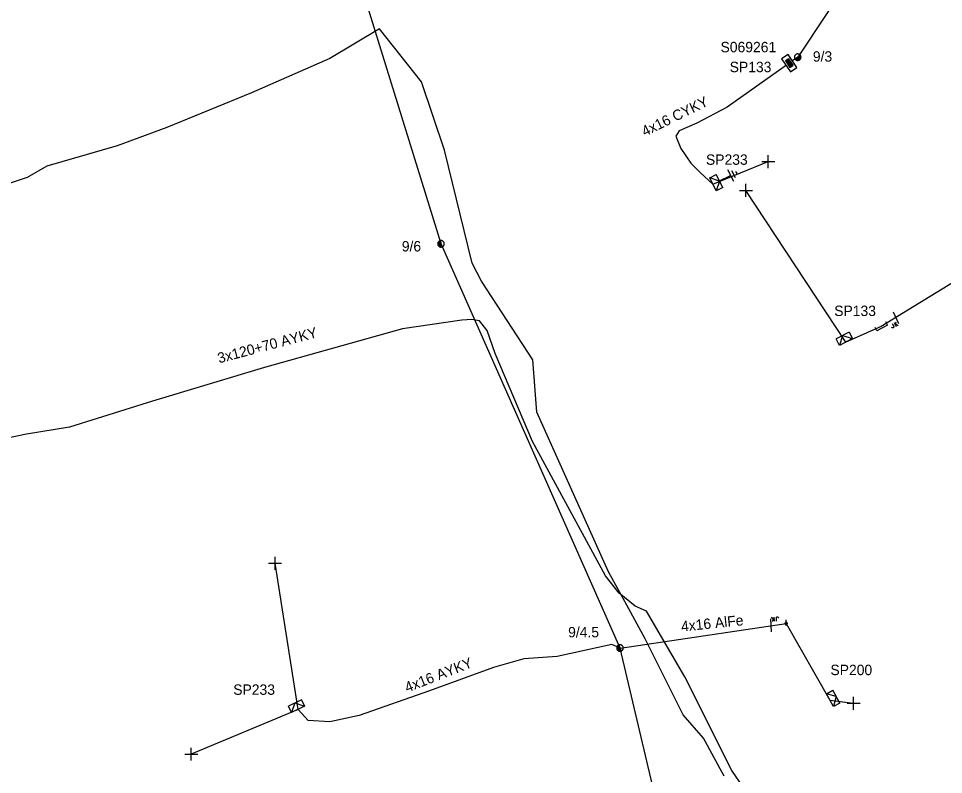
# Model space of a CAD drawing. Extents: x -717562 to -713845, y -1151196 to -1143903.
# Drawn here: x -717170 to -717081, y -1144446.2 to -1144373.5 of the extents above; entities that cross this region are included whole.
import ezdxf

# ---------------------------------------------------------------- set-up
doc = ezdxf.new("R2010")
doc.units = 0
for name, color, linetype in [('Vrstva 1', 7, 'Continuous'), ('Vrstva 12', 7, 'Continuous'), ('Vrstva 13', 7, 'Continuous'), ('Vrstva 14', 7, 'Continuous'), ('Vrstva 15', 7, 'Continuous'), ('Vrstva 18', 7, 'Continuous'), ('Vrstva 2', 7, 'Continuous'), ('Vrstva 28', 7, 'Continuous'), ('Vrstva 29', 7, 'Continuous'), ('Vrstva 30', 7, 'Continuous'), ('Vrstva 31', 7, 'Continuous'), ('Vrstva 33', 7, 'Continuous'), ('Vrstva 34', 7, 'Continuous'), ('Vrstva 4', 7, 'Continuous'), ('Vrstva 52', 7, 'Continuous'), ('Vrstva 53', 7, 'Continuous'), ('Vrstva 54', 7, 'Continuous'), ('Vrstva 59', 7, 'Continuous'), ('Vrstva 8', 7, 'Continuous'), ('Vrstva 9', 7, 'Continuous')]:
    doc.layers.add(name, color=color, linetype=linetype)

# ---------------------------------------------------------------- blocks, each defined once
blk = doc.blocks.new('NN440')
at = {"layer": 'Vrstva 2'}
for points in [[(0.63, 0), (0.63, 0.06), (0.62, 0.13), (0.6, 0.19), (0.58, 0.25), (0.55, 0.31), (0.51, 0.37), (0.47, 0.42), (0.42, 0.46), (0.37, 0.51), (0.32, 0.54), (0.26, 0.57), (0.2, 0.59), (0.13, 0.61), (0.07, 0.62), (0, 0.63), (-0.06, 0.62), (-0.13, 0.61), (-0.19, 0.59), (-0.26, 0.57), (-0.31, 0.54), (-0.37, 0.51), (-0.42, 0.46), (-0.47, 0.42), (-0.51, 0.37), (-0.54, 0.31), (-0.57, 0.25), (-0.6, 0.19), (-0.62, 0.13), (-0.63, 0.06), (-0.63, 0), (-0.63, -0.07), (-0.62, -0.14), (-0.6, -0.2), (-0.57, -0.26), (-0.54, -0.32), (-0.51, -0.37), (-0.47, -0.43), (-0.42, -0.47), (-0.37, -0.51), (-0.31, -0.55), (-0.26, -0.58), (-0.19, -0.6), (-0.13, -0.62), (-0.06, -0.63), (0, -0.63), (0.07, -0.63), (0.13, -0.62), (0.2, -0.6), (0.26, -0.58), (0.32, -0.55), (0.37, -0.51), (0.42, -0.47), (0.47, -0.43), (0.51, -0.37), (0.55, -0.32), (0.58, -0.26), (0.6, -0.2), (0.62, -0.14), (0.63, -0.07), (0.63, 0)], [(-0.63, 0), (0.63, 0)], [(-0.6, -0.18), (0.57, -0.18)], [(-0.51, -0.32), (0.5, -0.32)], [(-0.37, -0.47), (0.35, -0.47)]]:
    blk.add_lwpolyline(points, dxfattribs=at)
blk = doc.blocks.new('NN840')
at = {"layer": 'Vrstva 15'}
for points in [[(0.003, 0.619), (0.003, -0.631)], [(-0.745, -0.71), (-0.745, -0.66)], [(-0.73, -0.764), (-0.745, -0.71)], [(-0.657, -0.798), (-0.73, -0.764)], [(-0.627, -0.798), (-0.657, -0.798)], [(-0.558, -0.764), (-0.627, -0.798)], [(-0.538, -0.71), (-0.558, -0.764)], [(-0.538, -0.385), (-0.538, -0.71)], [(-0.332, -0.385), (-0.332, -0.798)], [(-0.332, -0.641), (-0.125, -0.385)], [(-0.263, -0.557), (-0.091, -0.798)]]:
    blk.add_lwpolyline(points, dxfattribs=at)
blk = doc.blocks.new('NN800')
at = {"layer": 'Vrstva 1'}
for points in [[(-0.442, 0.442), (0.442, -0.442)], [(-0.442, -0.442), (0.442, 0.442)]]:
    blk.add_lwpolyline(points, dxfattribs=at)
blk = doc.blocks.new('NN620')
at = {"layer": 'Vrstva 8'}
for points in [[(0.752, 0.004), (-0.748, 0.004)], [(-0.748, 0.004), (-0.748, -0.746)], [(0.752, -0.746), (0.752, 0.004)], [(-0.748, -0.746), (0.752, -0.746)], [(0.368, -0.18), (-0.376, -0.18)], [(-0.376, -0.18), (-0.376, -0.558)], [(-0.376, -0.558), (0.368, -0.558)], [(0.321, -0.227), (-0.329, -0.227)], [(-0.329, -0.227), (-0.329, -0.51)], [(-0.329, -0.51), (0.321, -0.51)], [(0.274, -0.274), (-0.281, -0.274)], [(-0.281, -0.274), (-0.281, -0.463)], [(-0.281, -0.463), (0.274, -0.463)], [(0.227, -0.321), (-0.234, -0.321)], [(-0.234, -0.321), (-0.234, -0.416)], [(-0.234, -0.416), (0.227, -0.416)], [(-0.193, -0.369), (0.185, -0.369)], [(0.227, -0.416), (0.227, -0.321)], [(0.274, -0.463), (0.274, -0.274)], [(0.321, -0.51), (0.321, -0.227)], [(0.368, -0.558), (0.368, -0.18)]]:
    blk.add_lwpolyline(points, dxfattribs=at)
blk = doc.blocks.new('NN630')
at = {"layer": 'Vrstva 9'}
for points in [[(-0.003, -0.7), (-0.703, 0)], [(-0.703, -0.7), (-0.703, 0), (0.697, 0), (0.697, -0.7)], [(-0.703, -0.7), (0.697, -0.7)], [(-0.003, -0.7), (0.697, 0)]]:
    blk.add_lwpolyline(points, dxfattribs=at)
blk = doc.blocks.new('NN810')
at = {"layer": 'Vrstva 14'}
for points in [[(0.004, -0.64), (0.004, -1.89)], [(0.629, -1.89), (-0.621, -1.89)], [(0.388, -2.2), (-0.399, -2.2)], [(0.004, -2.515), (-0.124, -2.515)], [(0.137, -2.515), (0.004, -2.515)]]:
    blk.add_lwpolyline(points, dxfattribs=at)
blk = doc.blocks.new('NN500')
at = {"layer": 'Vrstva 2'}
for points in [[(0, -0.24), (0.02, -0.23), (0.05, -0.23), (0.07, -0.22), (0.09, -0.22), (0.12, -0.2), (0.14, -0.19), (0.16, -0.18), (0.17, -0.16), (0.19, -0.14), (0.2, -0.12), (0.21, -0.1), (0.22, -0.07), (0.23, -0.05), (0.23, -0.02), (0.23, 0), (0.23, 0.02), (0.23, 0.05), (0.22, 0.07), (0.21, 0.1), (0.2, 0.12), (0.19, 0.14), (0.17, 0.16), (0.16, 0.17), (0.14, 0.19), (0.12, 0.2), (0.09, 0.21), (0.07, 0.22), (0.05, 0.23), (0.02, 0.23), (0, 0.23), (-0.03, 0.23), (-0.05, 0.23), (-0.07, 0.22), (-0.1, 0.21), (-0.12, 0.2), (-0.14, 0.19), (-0.16, 0.17), (-0.18, 0.16), (-0.19, 0.14), (-0.2, 0.12), (-0.22, 0.1), (-0.22, 0.07), (-0.23, 0.05), (-0.23, 0.02), (-0.24, 0), (-0.23, -0.02), (-0.23, -0.05), (-0.22, -0.07), (-0.22, -0.1), (-0.2, -0.12), (-0.19, -0.14), (-0.18, -0.16), (-0.16, -0.18), (-0.14, -0.19), (-0.12, -0.2), (-0.1, -0.22), (-0.07, -0.22), (-0.05, -0.23), (-0.03, -0.23), (0, -0.24)], [(0, -0.24), (0.02, -0.23), (0.05, -0.23), (0.07, -0.22), (0.09, -0.22), (0.12, -0.2), (0.14, -0.19), (0.16, -0.18), (0.17, -0.16), (0.19, -0.14), (0.2, -0.12), (0.21, -0.1), (0.22, -0.07), (0.23, -0.05), (0.23, -0.02), (0.23, 0), (0.23, 0.02), (0.23, 0.05), (0.22, 0.07), (0.21, 0.1), (0.2, 0.12), (0.19, 0.14), (0.17, 0.16), (0.16, 0.17), (0.14, 0.19), (0.12, 0.2), (0.09, 0.21), (0.07, 0.22), (0.05, 0.23), (0.02, 0.23), (0, 0.23), (-0.03, 0.23), (-0.05, 0.23), (-0.07, 0.22), (-0.1, 0.21), (-0.12, 0.2), (-0.14, 0.19), (-0.16, 0.17), (-0.18, 0.16), (-0.19, 0.14), (-0.2, 0.12), (-0.22, 0.1), (-0.22, 0.07), (-0.23, 0.05), (-0.23, 0.02), (-0.24, 0), (-0.23, -0.02), (-0.23, -0.05), (-0.22, -0.07), (-0.22, -0.1), (-0.2, -0.12), (-0.19, -0.14), (-0.18, -0.16), (-0.16, -0.18), (-0.14, -0.19), (-0.12, -0.2), (-0.1, -0.22), (-0.07, -0.22), (-0.05, -0.23), (-0.03, -0.23), (0, -0.24)], [(0, -0.21), (0.02, -0.2), (0.04, -0.2), (0.06, -0.2), (0.08, -0.19), (0.1, -0.18), (0.12, -0.17), (0.14, -0.15), (0.15, -0.14), (0.16, -0.12), (0.18, -0.1), (0.19, -0.08), (0.19, -0.06), (0.2, -0.04), (0.2, -0.02), (0.2, 0), (0.2, 0.02), (0.2, 0.04), (0.19, 0.06), (0.19, 0.08), (0.18, 0.1), (0.16, 0.12), (0.15, 0.14), (0.14, 0.15), (0.12, 0.17), (0.1, 0.18), (0.08, 0.19), (0.06, 0.19), (0.04, 0.2), (0.02, 0.2), (0, 0.2), (-0.02, 0.2), (-0.04, 0.2), (-0.06, 0.19), (-0.08, 0.19), (-0.1, 0.18), (-0.12, 0.17), (-0.14, 0.15), (-0.15, 0.14), (-0.17, 0.12), (-0.18, 0.1), (-0.19, 0.08), (-0.2, 0.06), (-0.2, 0.04), (-0.21, 0.02), (-0.21, 0), (-0.21, -0.02), (-0.2, -0.04), (-0.2, -0.06), (-0.19, -0.08), (-0.18, -0.1), (-0.17, -0.12), (-0.15, -0.14), (-0.14, -0.15), (-0.12, -0.17), (-0.1, -0.18), (-0.08, -0.19), (-0.06, -0.2), (-0.04, -0.2), (-0.02, -0.2), (0, -0.21)], [(0, -0.18), (0.02, -0.18), (0.04, -0.17), (0.05, -0.17), (0.07, -0.16), (0.09, -0.15), (0.1, -0.14), (0.12, -0.13), (0.13, -0.12), (0.14, -0.1), (0.15, -0.09), (0.16, -0.07), (0.17, -0.05), (0.17, -0.04), (0.17, -0.02), (0.17, 0), (0.17, 0.02), (0.17, 0.04), (0.17, 0.05), (0.16, 0.07), (0.15, 0.09), (0.14, 0.1), (0.13, 0.12), (0.12, 0.13), (0.1, 0.14), (0.09, 0.15), (0.07, 0.16), (0.05, 0.17), (0.04, 0.17), (0.02, 0.17), (0, 0.18), (-0.02, 0.17), (-0.04, 0.17), (-0.06, 0.17), (-0.07, 0.16), (-0.09, 0.15), (-0.1, 0.14), (-0.12, 0.13), (-0.13, 0.12), (-0.14, 0.1), (-0.15, 0.09), (-0.16, 0.07), (-0.17, 0.05), (-0.17, 0.04), (-0.18, 0.02), (-0.18, 0), (-0.18, -0.02), (-0.17, -0.04), (-0.17, -0.05), (-0.16, -0.07), (-0.15, -0.09), (-0.14, -0.1), (-0.13, -0.12), (-0.12, -0.13), (-0.1, -0.14), (-0.09, -0.15), (-0.07, -0.16), (-0.06, -0.17), (-0.04, -0.17), (-0.02, -0.18), (0, -0.18)], [(0, -0.15), (0.01, -0.15), (0.03, -0.14), (0.04, -0.14), (0.06, -0.13), (0.07, -0.13), (0.08, -0.12), (0.1, -0.11), (0.11, -0.1), (0.12, -0.09), (0.13, -0.07), (0.13, -0.06), (0.14, -0.05), (0.14, -0.03), (0.14, -0.02), (0.14, 0), (0.14, 0.01), (0.14, 0.03), (0.14, 0.04), (0.13, 0.06), (0.13, 0.07), (0.12, 0.09), (0.11, 0.1), (0.1, 0.11), (0.08, 0.12), (0.07, 0.13), (0.06, 0.13), (0.04, 0.14), (0.03, 0.14), (0.01, 0.14), (0, 0.15), (-0.02, 0.14), (-0.03, 0.14), (-0.05, 0.14), (-0.06, 0.13), (-0.07, 0.13), (-0.09, 0.12), (-0.1, 0.11), (-0.11, 0.1), (-0.12, 0.09), (-0.13, 0.07), (-0.13, 0.06), (-0.14, 0.04), (-0.14, 0.03), (-0.15, 0.01), (-0.15, 0), (-0.15, -0.02), (-0.14, -0.03), (-0.14, -0.05), (-0.13, -0.06), (-0.13, -0.07), (-0.12, -0.09), (-0.11, -0.1), (-0.1, -0.11), (-0.09, -0.12), (-0.07, -0.13), (-0.06, -0.13), (-0.05, -0.14), (-0.03, -0.14), (-0.02, -0.15), (0, -0.15)], [(0, -0.12), (0.01, -0.12), (0.02, -0.11), (0.03, -0.11), (0.05, -0.11), (0.06, -0.1), (0.07, -0.09), (0.08, -0.09), (0.09, -0.08), (0.09, -0.07), (0.1, -0.06), (0.11, -0.05), (0.11, -0.04), (0.11, -0.02), (0.11, -0.01), (0.12, 0), (0.11, 0.01), (0.11, 0.02), (0.11, 0.04), (0.11, 0.05), (0.1, 0.06), (0.09, 0.07), (0.09, 0.08), (0.08, 0.09), (0.07, 0.09), (0.06, 0.1), (0.05, 0.11), (0.03, 0.11), (0.02, 0.11), (0.01, 0.12), (0, 0.12), (-0.01, 0.12), (-0.03, 0.11), (-0.04, 0.11), (-0.05, 0.11), (-0.06, 0.1), (-0.07, 0.09), (-0.08, 0.09), (-0.09, 0.08), (-0.1, 0.07), (-0.1, 0.06), (-0.11, 0.05), (-0.11, 0.04), (-0.12, 0.02), (-0.12, 0.01), (-0.12, 0), (-0.12, -0.01), (-0.12, -0.02), (-0.11, -0.04), (-0.11, -0.05), (-0.1, -0.06), (-0.1, -0.07), (-0.09, -0.08), (-0.08, -0.09), (-0.07, -0.09), (-0.06, -0.1), (-0.05, -0.11), (-0.04, -0.11), (-0.03, -0.11), (-0.01, -0.12), (0, -0.12)], [(0, -0.09), (0.01, -0.09), (0.02, -0.09), (0.03, -0.08), (0.03, -0.08), (0.04, -0.08), (0.05, -0.07), (0.06, -0.07), (0.06, -0.06), (0.07, -0.05), (0.07, -0.04), (0.08, -0.04), (0.08, -0.03), (0.08, -0.02), (0.09, -0.01), (0.09, 0), (0.09, 0.01), (0.08, 0.02), (0.08, 0.03), (0.08, 0.03), (0.07, 0.04), (0.07, 0.05), (0.06, 0.06), (0.06, 0.06), (0.05, 0.07), (0.04, 0.07), (0.03, 0.08), (0.03, 0.08), (0.02, 0.08), (0.01, 0.09), (0, 0.09), (-0.01, 0.09), (-0.02, 0.08), (-0.03, 0.08), (-0.04, 0.08), (-0.04, 0.07), (-0.05, 0.07), (-0.06, 0.06), (-0.07, 0.06), (-0.07, 0.05), (-0.08, 0.04), (-0.08, 0.03), (-0.08, 0.03), (-0.09, 0.02), (-0.09, 0.01), (-0.09, 0), (-0.09, -0.01), (-0.09, -0.02), (-0.08, -0.03), (-0.08, -0.04), (-0.08, -0.04), (-0.07, -0.05), (-0.07, -0.06), (-0.06, -0.07), (-0.05, -0.07), (-0.04, -0.08), (-0.04, -0.08), (-0.03, -0.08), (-0.02, -0.09), (-0.01, -0.09), (0, -0.09)], [(0, -0.06), (0, -0.06), (0.01, -0.06), (0.02, -0.05), (0.02, -0.05), (0.03, -0.05), (0.03, -0.05), (0.04, -0.04), (0.04, -0.04), (0.05, -0.03), (0.05, -0.03), (0.05, -0.02), (0.05, -0.02), (0.05, -0.01), (0.06, -0.01), (0.06, 0), (0.06, 0.01), (0.05, 0.01), (0.05, 0.02), (0.05, 0.02), (0.05, 0.03), (0.05, 0.03), (0.04, 0.04), (0.04, 0.04), (0.03, 0.05), (0.03, 0.05), (0.02, 0.05), (0.02, 0.05), (0.01, 0.06), (0, 0.06), (0, 0.06), (-0.01, 0.06), (-0.01, 0.06), (-0.02, 0.05), (-0.02, 0.05), (-0.03, 0.05), (-0.03, 0.05), (-0.04, 0.04), (-0.04, 0.04), (-0.05, 0.03), (-0.05, 0.03), (-0.05, 0.02), (-0.06, 0.02), (-0.06, 0.01), (-0.06, 0.01), (-0.06, 0), (-0.06, -0.01), (-0.06, -0.01), (-0.06, -0.02), (-0.05, -0.02), (-0.05, -0.03), (-0.05, -0.03), (-0.04, -0.04), (-0.04, -0.04), (-0.03, -0.05), (-0.03, -0.05), (-0.02, -0.05), (-0.02, -0.05), (-0.01, -0.06), (-0.01, -0.06), (0, -0.06)], [(0, -0.03), (0, -0.03), (0, -0.03), (0.01, -0.03), (0.01, -0.03), (0.01, -0.02), (0.02, -0.02), (0.02, -0.02), (0.02, -0.02), (0.02, -0.02), (0.02, -0.01), (0.02, -0.01), (0.03, -0.01), (0.03, -0.01), (0.03, 0), (0.03, 0), (0.03, 0), (0.03, 0.01), (0.03, 0.01), (0.02, 0.01), (0.02, 0.01), (0.02, 0.02), (0.02, 0.02), (0.02, 0.02), (0.02, 0.02), (0.01, 0.02), (0.01, 0.02), (0.01, 0.03), (0, 0.03), (0, 0.03), (0, 0.03), (0, 0.03), (-0.01, 0.03), (-0.01, 0.03), (-0.01, 0.02), (-0.02, 0.02), (-0.02, 0.02), (-0.02, 0.02), (-0.02, 0.02), (-0.02, 0.02), (-0.03, 0.01), (-0.03, 0.01), (-0.03, 0.01), (-0.03, 0.01), (-0.03, 0), (-0.03, 0), (-0.03, 0), (-0.03, -0.01), (-0.03, -0.01), (-0.03, -0.01), (-0.03, -0.01), (-0.02, -0.02), (-0.02, -0.02), (-0.02, -0.02), (-0.02, -0.02), (-0.02, -0.02), (-0.01, -0.03), (-0.01, -0.03), (-0.01, -0.03), (0, -0.03), (0, -0.03)], [(0.23, 0), (0.7, 0)]]:
    blk.add_lwpolyline(points, dxfattribs=at)
blk = doc.blocks.new('NN515')
at = {"layer": 'Vrstva 2'}
for points in [[(-0.59, 0.176), (0.591, 0.176)], [(-0.59, 0.176), (-0.59, -0.179)], [(0.591, 0.176), (0.591, -0.179)]]:
    blk.add_lwpolyline(points, dxfattribs=at)

msp = doc.modelspace()

# ---------------------------------------------------------------- linework, layer by layer
at = {"layer": 'Vrstva 1'}
msp.add_lwpolyline([(-717063.536, -1144519.499), (-717088.976, -1144491.919), (-717104.646, -1144465.559), (-717112.106, -1144434.029), (-717129.316, -1144395.139), (-717142.076, -1144353.909)], dxfattribs=at)
at = {"layer": 'Vrstva 4'}
for points in [[(-717058.966, -1144385.939), (-717086.976, -1144403.089), (-717090.376, -1144404.589)], [(-717112.106, -1144434.029), (-717096.126, -1144431.679), (-717091.927, -1144439.039)]]:
    msp.add_lwpolyline(points, dxfattribs=at)
at = {"layer": 'Vrstva 52'}
for points in [[(-717080.996, -1144356.058), (-717095.016, -1144377.189), (-717095.524, -1144377.548)], [(-717102.09, -1144446.37), (-717104.09, -1144442.69), (-717106.02, -1144440.45), (-717109.7, -1144433.13), (-717111.46, -1144429.92), (-717113.22, -1144426.71), (-717120.1, -1144411.35), (-717120.48, -1144406.29), (-717125.42, -1144398.75), (-717126.323, -1144397.007), (-717128.97, -1144386.14), (-717131.18, -1144379.56), (-717135.25, -1144374.45), (-717140.01, -1144377.32), (-717147.54, -1144380.61), (-717155.69, -1144383.96), (-717160.45, -1144385.72), (-717167.22, -1144387.68), (-717169.11, -1144388.76), (-717173.38, -1144390.19)], [(-717096.084, -1144377.945), (-717101.796, -1144381.989), (-717104.726, -1144383.549), (-717106.426, -1144384.289), (-717106.746, -1144384.779), (-717106.266, -1144385.969), (-717105.306, -1144387.399), (-717104.366, -1144388.299), (-717103.166, -1144389.418)], [(-717096.276, -1144453.199), (-717101.366, -1144445.809), (-717105.866, -1144436.809), (-717109.556, -1144430.469), (-717110.656, -1144429.999), (-717112.176, -1144428.739), (-717113.506, -1144427.099), (-717120.506, -1144414.149), (-717124.096, -1144405.709), (-717124.896, -1144403.479), (-717125.626, -1144402.559), (-717126.366, -1144402.419), (-717127.326, -1144402.479), (-717133.036, -1144403.329), (-717146.296, -1144407.029), (-717157.056, -1144410.269), (-717165.056, -1144412.769), (-717169.196, -1144413.459), (-717173.626, -1144414.379), (-717175.307, -1144414.629)], [(-717112.106, -1144434.029), (-717112.886, -1144433.699), (-717118.146, -1144434.839), (-717121.366, -1144435.069), (-717124.286, -1144435.919), (-717130.426, -1144438.149), (-717137.196, -1144440.529), (-717140.016, -1144441.119), (-717142.086, -1144440.999), (-717143.067, -1144439.939)]]:
    msp.add_lwpolyline(points, dxfattribs=at)
at = {"layer": 'Vrstva 59'}
for points in [[(-717103.166, -1144389.418), (-717097.85, -1144387.232)], [(-717090.376, -1144404.589), (-717100, -1144390)], [(-717143.067, -1144439.939), (-717145.279, -1144425.871)], [(-717091.927, -1144439.039), (-717089.65, -1144439.348)], [(-717143.067, -1144439.939), (-717153.339, -1144444.241)]]:
    msp.add_lwpolyline(points, dxfattribs=at)

# ---------------------------------------------------------------- block references
at = {"layer": 'Vrstva 13', "xscale": 0.5}
for name, p, yscale, rotation in [('NN440', (-717095.016, -1144377.189), 0.5000000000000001, 34.33799449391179), ('NN440', (-717129.316, -1144395.139), 0.5, -74.4836999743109), ('NN500', (-717096.126, -1144431.679), 0.5, 90), ('NN440', (-717112.106, -1144434.029), 0.5, -67.12203328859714)]:
    msp.add_blockref(name, p, dxfattribs=dict(at, yscale=yscale, rotation=rotation))
at = {"layer": 'Vrstva 13', "rotation": -152.0405111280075}
msp.add_blockref('NN515', (-717086.976, -1144403.089), dxfattribs=at)
at = {"layer": 'Vrstva 15', "rotation": 116.98360557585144}
msp.add_blockref('NN810', (-717103.167, -1144389.42), dxfattribs=at)
at = {"layer": 'Vrstva 18'}
for p, rotation in [((-717085.588, -1144402.239), 24.187252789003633), ((-717097.562, -1144431.866), -176.35592769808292)]:
    msp.add_blockref('NN840', p, dxfattribs=dict(at, rotation=rotation))
at = {"layer": 'Vrstva 28', "rotation": -55.53592405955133}
msp.add_blockref('NN620', (-717095.524, -1144377.548), dxfattribs=at)
at = {"layer": 'Vrstva 31'}
for p, rotation in [((-717103.166, -1144389.419), 116.98360557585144), ((-717090.376, -1144404.589), -152.0405111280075), ((-717091.926, -1144439.039), 118.52124430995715), ((-717143.066, -1144439.939), -154.3398528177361)]:
    msp.add_blockref('NN630', p, dxfattribs=dict(at, rotation=rotation))
at = {"layer": 'Vrstva 34'}
for p, rotation in [((-717097.85, -1144387.233), 45), ((-717100, -1144390), 45), ((-717145.279, -1144425.871), 45), ((-717089.65, -1144439.348), 45), ((-717153.339, -1144444.241), 45.000000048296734)]:
    msp.add_blockref('NN800', p, dxfattribs=dict(at, rotation=rotation))

# ---------------------------------------------------------------- texts
at = {"layer": 'Vrstva 12'}
for s, p in [('9/3', (-717093.561, -1144377.621)), ('9/6', (-717133.089, -1144395.879)), ('9/4.5', (-717117.095, -1144433.004))]:
    msp.add_text(s, height=1, dxfattribs=at).set_placement(p)
at = {"layer": 'Vrstva 29'}
msp.add_text('S069261', height=1, dxfattribs=at).set_placement((-717102.439, -1144376.715))
at = {"layer": 'Vrstva 30'}
msp.add_text('SP133', height=1, dxfattribs=at).set_placement((-717101.558, -1144378.63))
at = {"layer": 'Vrstva 33'}
for s, p in [('SP233', (-717103.838, -1144387.542)), ('SP133', (-717091.506, -1144402.09)), ('SP200', (-717091.87, -1144436.636)), ('SP233', (-717149.3, -1144438.532))]:
    msp.add_text(s, height=1, dxfattribs=at).set_placement(p)
at = {"layer": 'Vrstva 53'}
msp.add_text('4x16 AlFe', height=1, rotation=5.983, dxfattribs=at).set_placement((-717106.181, -1144432.456))
at = {"layer": 'Vrstva 54'}
for s, rotation, p in [('4x16 CYKY', 26.134, (-717109.719, -1144384.841)), ('3x120+70 AYKY', 14.914, (-717150.655, -1144406.647)), ('4x16 AYKY', 21.355, (-717132.571, -1144438.326))]:
    msp.add_text(s, height=1, rotation=rotation, dxfattribs=at).set_placement(p)

doc.saveas('drawing.dxf')
